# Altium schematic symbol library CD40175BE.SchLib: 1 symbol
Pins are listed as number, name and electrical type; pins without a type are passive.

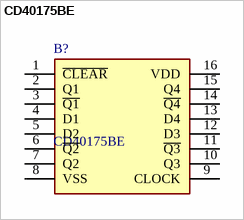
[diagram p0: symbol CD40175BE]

## CD40175BE
designator B?
Texas Instruments CD40175BE Quad D Type Flip Flop IC, CMOS, 16-Pin PDIP; Geometry.Height: 5.08mm
footprint DIP794W53P254L1930H508Q16N
pins: 1 ~{CLEAR}, 2 Q1, 3 ~{Q1}, 4 D1, 5 D2, 6 ~{Q2}, 7 Q2, 8 VSS, 9 CLOCK, 10 Q3, 11 ~{Q3}, 12 D3, 13 D4, 14 ~{Q4}, 15 Q4, 16 VDD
